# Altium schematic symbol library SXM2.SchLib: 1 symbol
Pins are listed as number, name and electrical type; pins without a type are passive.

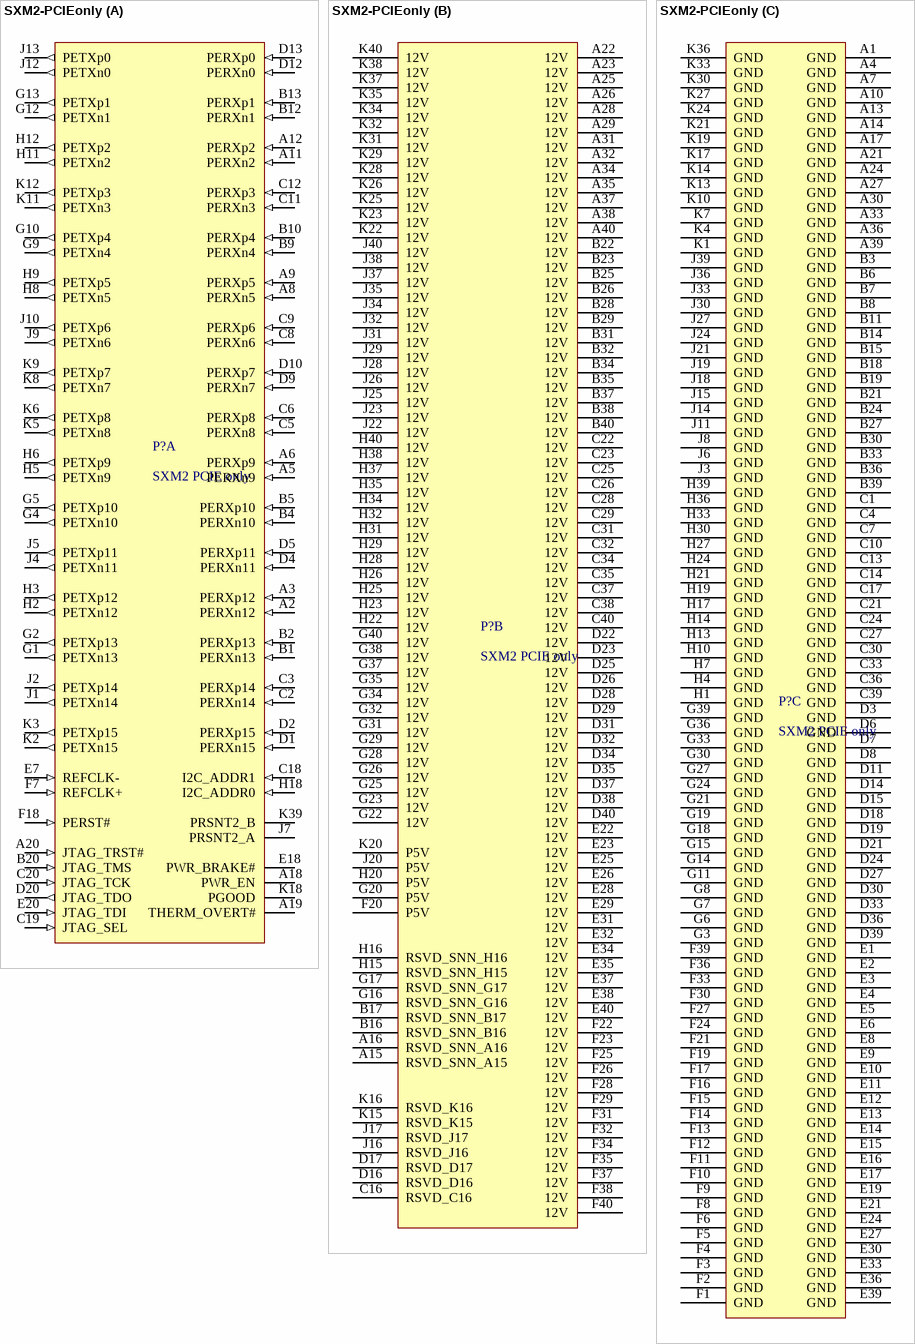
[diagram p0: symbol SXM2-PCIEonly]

## SXM2-PCIEonly
designator P?, comment SXM2 PCIE only
footprint SXM2_PCIEonly
part A pins: A2 PERXn12 (in), A3 PERXp12 (in), A5 PERXn9 (in), A6 PERXp9 (in), A8 PERXn5 (in), A9 PERXp5 (in), A11 PERXn2 (in), A12 PERXp2 (in), A18 PWR_EN, A19 THERM_OVERT#, A20 JTAG_TRST# (in), B1 PERXn13 (in), B2 PERXp13 (in), B4 PERXn10 (in), B5 PERXp10 (in), B9 PERXn4 (in), B10 PERXp4 (in), B12 PERXn1 (in), B13 PERXp1 (in), B20 JTAG_TMS (in), C2 PERXn14 (in), C3 PERXp14 (in), C5 PERXn8 (in), C6 PERXp8 (in), C8 PERXn6 (in), C9 PERXp6 (in), C11 PERXn3 (in), C12 PERXp3 (in), C18 I2C_ADDR1 (in), C19 JTAG_SEL (in), C20 JTAG_TCK (in), D1 PERXn15 (in), D2 PERXp15 (in), D4 PERXn11 (in), D5 PERXp11 (in), D9 PERXn7 (in), D10 PERXp7 (in), D12 PERXn0 (in), D13 PERXp0 (in), D20 JTAG_TDO (out), E7 REFCLK- (in), E18 PWR_BRAKE#, E20 JTAG_TDI (in), F7 REFCLK+ (in), F18 PERST# (in), G1 PETXn13 (out), G2 PETXp13 (out), G4 PETXn10 (out), G5 PETXp10 (out), G9 PETXn4 (out), G10 PETXp4 (out), G12 PETXn1 (out), G13 PETXp1 (out), H2 PETXn12 (out), H3 PETXp12 (out), H5 PETXn9 (out), H6 PETXp9 (out), H8 PETXn5 (out), H9 PETXp5 (out), H11 PETXn2 (out), H12 PETXp2 (out), H18 I2C_ADDR0 (in), J1 PETXn14 (out), J2 PETXp14 (out), J4 PETXn11 (out), J5 PETXp11 (out), J7 PRSNT2_A, J9 PETXn6 (out), J10 PETXp6 (out), J12 PETXn0 (out), J13 PETXp0 (out), K2 PETXn15 (out), K3 PETXp15 (out), K5 PETXn8 (out), K6 PETXp8 (out), K8 PETXn7 (out), K9 PETXp7 (out), K11 PETXn3 (out), K12 PETXp3 (out), K18 PGOOD, K39 PRSNT2_B
part B pins: A15 RSVD_SNN_A15 (power), A16 RSVD_SNN_A16 (power), A22 12V (power), A23 12V (power), A25 12V (power), A26 12V (power), A28 12V (power), A29 12V (power), A31 12V (power), A32 12V (power), A34 12V (power), A35 12V (power), A37 12V (power), A38 12V (power), A40 12V (power), B16 RSVD_SNN_B16 (power), B17 RSVD_SNN_B17 (power), B22 12V (power), B23 12V (power), B25 12V (power), B26 12V (power), B28 12V (power), B29 12V (power), B31 12V (power), B32 12V (power), B34 12V (power), B35 12V (power), B37 12V (power), B38 12V (power), B40 12V (power), C16 RSVD_C16 (power), C22 12V (power), C23 12V (power), C25 12V (power), C26 12V (power), C28 12V (power), C29 12V (power), C31 12V (power), C32 12V (power), C34 12V (power), C35 12V (power), C37 12V (power), C38 12V (power), C40 12V (power), D16 RSVD_D16 (power), D17 RSVD_D17 (power), D22 12V (power), D23 12V (power), D25 12V (power), D26 12V (power), D28 12V (power), D29 12V (power), D31 12V (power), D32 12V (power), D34 12V (power), D35 12V (power), D37 12V (power), D38 12V (power), D40 12V (power), E22 12V (power), E23 12V (power), E25 12V (power), E26 12V (power), E28 12V (power), E29 12V (power), E31 12V (power), E32 12V (power), E34 12V (power), E35 12V (power), E37 12V (power), E38 12V (power), E40 12V (power), F20 P5V (power), F22 12V (power), F23 12V (power), F25 12V (power), F26 12V (power), F28 12V (power), F29 12V (power), F31 12V (power), F32 12V (power), F34 12V (power), F35 12V (power), F37 12V (power), F38 12V (power), F40 12V (power), G16 RSVD_SNN_G16 (power), G17 RSVD_SNN_G17 (power), G20 P5V (power), G22 12V (power), G23 12V (power), G25 12V (power), G26 12V (power), G28 12V (power), G29 12V (power), G31 12V (power), G32 12V (power), G34 12V (power), G35 12V (power), G37 12V (power), G38 12V (power), G40 12V (power), H15 RSVD_SNN_H15 (power), H16 RSVD_SNN_H16 (power), H20 P5V (power), H22 12V (power), H23 12V (power), H25 12V (power), H26 12V (power), H28 12V (power), H29 12V (power), H31 12V (power), H32 12V (power), H34 12V (power), H35 12V (power), H37 12V (power), H38 12V (power), H40 12V (power), J16 RSVD_J16 (power), J17 RSVD_J17 (power), J20 P5V (power), J22 12V (power), J23 12V (power), J25 12V (power), J26 12V (power), J28 12V (power), J29 12V (power), J31 12V (power), J32 12V (power), J34 12V (power), J35 12V (power), J37 12V (power), J38 12V (power), J40 12V (power), K15 RSVD_K15 (power), K16 RSVD_K16 (power), K20 P5V (power), K22 12V (power), K23 12V (power), K25 12V (power), K26 12V (power), K28 12V (power), K29 12V (power), K31 12V (power), K32 12V (power), K34 12V (power), K35 12V (power), K37 12V (power), K38 12V (power), K40 12V (power)
part C pins: A1 GND (power), A4 GND (power), A7 GND (power), A10 GND (power), A13 GND (power), A14 GND (power), A17 GND (power), A21 GND (power), A24 GND (power), A27 GND (power), A30 GND (power), A33 GND (power), A36 GND (power), A39 GND (power), B3 GND (power), B6 GND (power), B7 GND (power), B8 GND (power), B11 GND (power), B14 GND (power), B15 GND (power), B18 GND (power), B19 GND (power), B21 GND (power), B24 GND (power), B27 GND (power), B30 GND (power), B33 GND (power), B36 GND (power), B39 GND (power), C1 GND (power), C4 GND (power), C7 GND (power), C10 GND (power), C13 GND (power), C14 GND (power), C17 GND (power), C21 GND (power), C24 GND (power), C27 GND (power), C30 GND (power), C33 GND (power), C36 GND (power), C39 GND (power), D3 GND (power), D6 GND (power), D7 GND (power), D8 GND (power), D11 GND (power), D14 GND (power), D15 GND (power), D18 GND (power), D19 GND (power), D21 GND (power), D24 GND (power), D27 GND (power), D30 GND (power), D33 GND (power), D36 GND (power), D39 GND (power), E1 GND (power), E2 GND (power), E3 GND (power), E4 GND (power), E5 GND (power), E6 GND (power), E8 GND (power), E9 GND (power), E10 GND (power), E11 GND (power), E12 GND (power), E13 GND (power), E14 GND (power), E15 GND (power), E16 GND (power), E17 GND (power), E19 GND (power), E21 GND (power), E24 GND (power), E27 GND (power), E30 GND (power), E33 GND (power), E36 GND (power), E39 GND (power), F1 GND (power), F2 GND (power), F3 GND (power), F4 GND (power), F5 GND (power), F6 GND (power), F8 GND (power), F9 GND (power), F10 GND (power), F11 GND (power), F12 GND (power), F13 GND (power), F14 GND (power), F15 GND (power), F16 GND (power), F17 GND (power), F19 GND (power), F21 GND (power), F24 GND (power), F27 GND (power), F30 GND (power), F33 GND (power), F36 GND (power), F39 GND (power), G3 GND (power), G6 GND (power), G7 GND (power), G8 GND (power), G11 GND (power), G14 GND (power), G15 GND (power), G18 GND (power), G19 GND (power), G21 GND (power), G24 GND (power), G27 GND (power), G30 GND (power), G33 GND (power), G36 GND (power), G39 GND (power), H1 GND (power), H4 GND (power), H7 GND (power), H10 GND (power), H13 GND (power), H14 GND (power), H17 GND (power), H19 GND (power), H21 GND (power), H24 GND (power), H27 GND (power), H30 GND (power), H33 GND (power), H36 GND (power), H39 GND (power), J3 GND (power), J6 GND (power), J8 GND (power), J11 GND (power), J14 GND (power), J15 GND (power), J18 GND (power), J19 GND (power), J21 GND (power), J24 GND (power), J27 GND (power), J30 GND (power), J33 GND (power), J36 GND (power), J39 GND (power), K1 GND (power), K4 GND (power), K7 GND (power), K10 GND (power), K13 GND (power), K14 GND (power), K17 GND (power), K19 GND (power), K21 GND (power), K24 GND (power), K27 GND (power), K30 GND (power), K33 GND (power), K36 GND (power)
